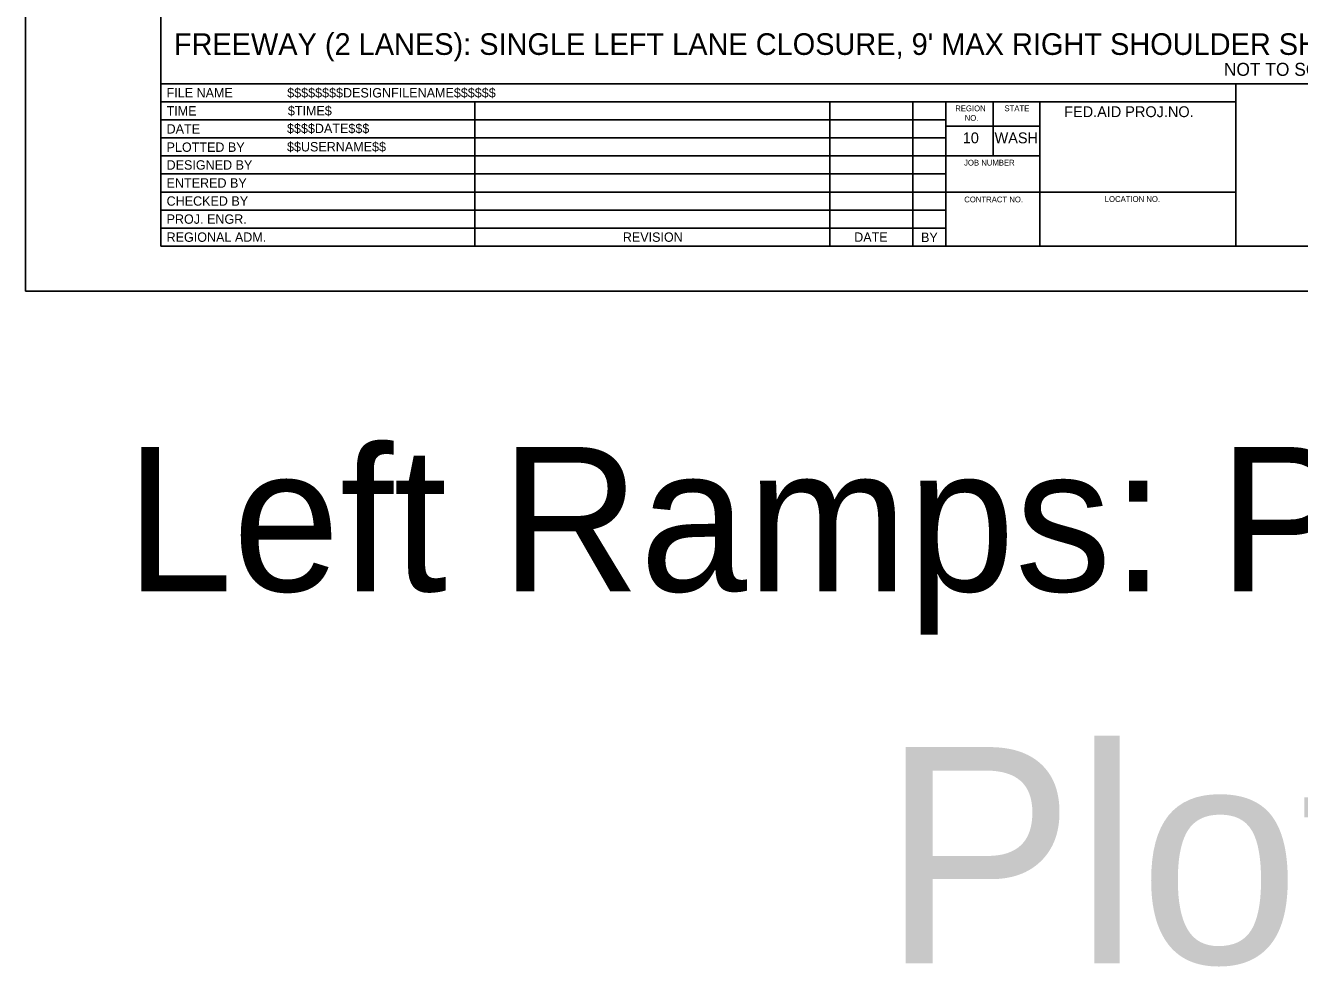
# Model space of a CAD drawing. Extents: x 99999 to 100116, y 99995 to 100013.
# Drawn here: x 100059.06 to 100067.9, y 99995.01 to 100001.53 of the extents above; entities that cross this region are included whole.
import ezdxf

# ---------------------------------------------------------------- set-up
doc = ezdxf.new("R2010")
doc.units = 0
for name, color, linetype in [('SH_DE_DetailHeading1Text', 7, 'Continuous'), ('SH_GI_PlotLimits', 7, 'Continuous'), ('SH_GI_SheetBorder', 7, 'Continuous'), ('SH_GI_SheetLocationText', 7, 'Continuous'), ('SH_GI_SheetTextInCells', 7, 'Continuous'), ('SH_GI_TitleBlockText', 7, 'Continuous')]:
    doc.layers.add(name, color=color, linetype=linetype)

msp = doc.modelspace()

# ---------------------------------------------------------------- linework, layer by layer
at = {"layer": 'SH_GI_PlotLimits'}
msp.add_lwpolyline([(100059.0625, 99999.6875), (100076.0625, 99999.6875), (100076.0625, 100010.6875), (100059.0625, 100010.6875)], close=True, dxfattribs=at)
at = {"layer": 'SH_GI_SheetBorder'}
for p, q in [((100060, 100010.375), (100060, 100000)), ((100060, 100001.1259), (100075.75, 100001.1259)), ((100067.4566, 100000), (100067.4566, 100001.1259)), ((100060, 100001.0008), (100067.4566, 100001.0008)), ((100062.179, 100001.0008), (100062.179, 100000)), ((100064.641, 100001.0008), (100064.641, 100000)), ((100065.2164, 100001.0008), (100065.2164, 100000)), ((100065.4451, 100001.0008), (100065.4451, 100000)), ((100065.7719, 100000.6255), (100065.7719, 100001.0008)), ((100066.0956, 100000), (100066.0956, 100001.0008)), ((100060, 100000.8757), (100062.1821, 100000.8757)), ((100062.1821, 100000.8757), (100065.4466, 100000.8757)), ((100060, 100000.7506), (100062.1821, 100000.7506)), ((100062.1821, 100000.7506), (100065.4466, 100000.7506)), ((100066.0958, 100000.831), (100065.4466, 100000.831)), ((100060, 100000.6255), (100065.4466, 100000.6255)), ((100066.0958, 100000.6255), (100065.4466, 100000.6255)), ((100060, 100000.5004), (100065.4466, 100000.5004)), ((100060, 100000.3753), (100065.4466, 100000.3753)), ((100067.4566, 100000.3753), (100065.4466, 100000.3753)), ((100060, 100000.2502), (100065.4466, 100000.2502)), ((100060, 100000.1251), (100065.4466, 100000.1251)), ((100060, 100000), (100075.75, 100000))]:
    msp.add_line(p, q, dxfattribs=at)

# ---------------------------------------------------------------- texts
at = {"layer": 'SH_DE_DetailHeading1Text'}
for s, height, p in [("FREEWAY (2 LANES): SINGLE LEFT LANE CLOSURE, 9' MAX RIGHT SHOULDER SHIFT (45 MPH WORK ZONE SPEED LIMIT, 40 MPH ADVISORY SPEED)", 0.15, (100060.0913, 100001.3259)), ('NOT TO SCALE', 0.09, (100067.3727, 100001.1809))]:
    msp.add_text(s, height=height, rotation=360, dxfattribs=at).set_placement(p)
at = {"layer": 'SH_GI_SheetLocationText'}
for s, height, p in [('Left Ramps: Parallel On-Ramp', 1, (100059.7551, 99997.6071)), ('Plot 4', 1.5, (100065.0007, 99995.0267))]:
    msp.add_text(s, height=height, dxfattribs=at).set_placement(p)
at = {"layer": 'SH_GI_SheetTextInCells'}
for s, height, p in [('FILE NAME', 0.06505, (100060.041, 100001.0308)), ('TIME', 0.06505, (100060.041, 100000.9057)), ('REGION', 0.04003, (100065.5099, 100000.9352)), ('STATE', 0.04003, (100065.8511, 100000.9357)), ('FED.AID PROJ.NO.', 0.07506, (100066.2652, 100000.8945)), ('DATE', 0.06505, (100060.041, 100000.7806)), ('NO.', 0.04003, (100065.5752, 100000.869)), ('10', 0.07506, (100065.5621, 100000.7131)), ('WASH', 0.07506, (100065.7826, 100000.7131)), ('PLOTTED BY', 0.06505, (100060.041, 100000.6538)), ('DESIGNED BY', 0.065052, (100060.041, 100000.5304)), ('JOB NUMBER', 0.04003, (100065.5712, 100000.5587)), ('ENTERED BY', 0.06505, (100060.041, 100000.4053)), ('CHECKED BY', 0.06505, (100060.041, 100000.2802)), ('CONTRACT NO.', 0.040032, (100065.5725, 100000.3037)), ('LOCATION NO.', 0.040032, (100066.5465, 100000.3067)), ('PROJ. ENGR.', 0.065052, (100060.041, 100000.1551)), ('REGIONAL ADM.', 0.065052, (100060.041, 100000.03)), ('REVISION', 0.06505, (100063.2048, 100000.03)), ('DATE', 0.06505, (100064.8091, 100000.03)), ('BY', 0.06505, (100065.2725, 100000.0285))]:
    msp.add_text(s, height=height, dxfattribs=at).set_placement(p)
at = {"layer": 'SH_GI_TitleBlockText'}
for s, height, p in [('$$$$$$$$DESIGNFILENAME$$$$$$', 0.065052, (100060.8775, 100001.0308)), ('$TIME$', 0.06505, (100060.882, 100000.9059)), ('$$$$DATE$$$', 0.065052, (100060.8759, 100000.7835)), ('$$USERNAME$$', 0.065052, (100060.8759, 100000.6567))]:
    msp.add_text(s, height=height, dxfattribs=at).set_placement(p)

doc.saveas('drawing.dxf')
